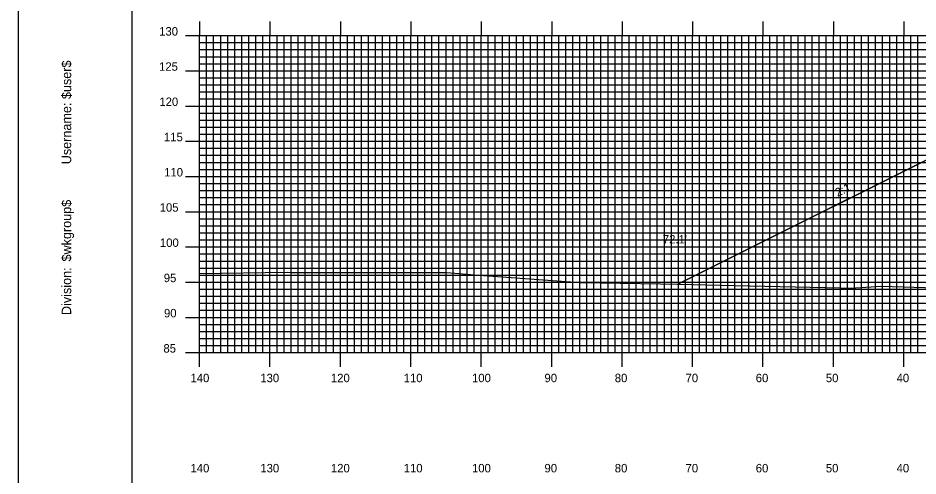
# Model space of a CAD drawing. Extents: x 1786189 to 1786532, y 442591 to 442811.
# Drawn here: x 1786188.8 to 1786316.6, y 442656.2 to 442721.2 of the extents above; entities that cross this region are included whole.
import ezdxf

# ---------------------------------------------------------------- set-up
doc = ezdxf.new("R2010")
doc.units = 0
for name, color, linetype in [('ANNOTATION', 7, 'Continuous'), ('BORDER', 7, 'Continuous'), ('D_Roadway_Centerline', 7, 'Continuous'), ('D_Roadway_SlopeLines', 7, 'Continuous'), ('D_Text_Standard', 7, 'Continuous'), ('H_V ANNOTATION', 7, 'Continuous'), ('MAJOR', 7, 'Continuous'), ('MINOR', 7, 'Continuous'), ('PLOT BOUNDARY', 7, 'Continuous'), ('S_Roadway_Centerline', 7, 'Continuous')]:
    doc.layers.add(name, color=color, linetype=linetype)

msp = doc.modelspace()

# ---------------------------------------------------------------- linework, layer by layer
at = {"layer": 'BORDER'}
msp.add_lwpolyline([(1786204.96, 442596.67), (1786524.96, 442596.67), (1786524.96, 442806.67), (1786204.96, 442806.67)], close=True, dxfattribs=at)
at = {"layer": 'D_Roadway_Centerline'}
msp.add_lwpolyline([(1786282.49, 442683.37), (1786326.75, 442705.5), (1786331.56, 442707.91), (1786334.56, 442708.03), (1786342.56, 442708.35), (1786354.56, 442708.61), (1786366.56, 442708.87), (1786374.56, 442708.55), (1786377.56, 442708.43), (1786382.31, 442706.06), (1786430.92, 442681.76)], dxfattribs=at)
at = {"layer": 'D_Roadway_SlopeLines'}
msp.add_lwpolyline([(1786331.56, 442707.91), (1786282.49, 442683.37)], dxfattribs=at)
at = {"layer": 'MAJOR'}
for p, q in [((1786214.56, 442720.67), (1786214.56, 442718.67)), ((1786224.56, 442720.67), (1786224.56, 442718.67)), ((1786234.56, 442720.67), (1786234.56, 442718.67)), ((1786244.56, 442720.67), (1786244.56, 442718.67)), ((1786254.56, 442720.67), (1786254.56, 442718.67)), ((1786264.56, 442720.67), (1786264.56, 442718.67)), ((1786274.56, 442720.67), (1786274.56, 442718.67)), ((1786284.56, 442720.67), (1786284.56, 442718.67)), ((1786294.56, 442720.67), (1786294.56, 442718.67)), ((1786304.56, 442720.67), (1786304.56, 442718.67)), ((1786314.56, 442720.67), (1786314.56, 442718.67)), ((1786212.56, 442718.67), (1786214.56, 442718.67)), ((1786214.56, 442718.67), (1786494.56, 442718.67)), ((1786214.56, 442673.67), (1786214.56, 442718.67)), ((1786214.56, 442673.67), (1786214.56, 442718.67)), ((1786214.56, 442718.67), (1786494.56, 442718.67)), ((1786224.56, 442673.67), (1786224.56, 442718.67)), ((1786234.56, 442673.67), (1786234.56, 442718.67)), ((1786244.56, 442673.67), (1786244.56, 442718.67)), ((1786254.56, 442673.67), (1786254.56, 442718.67)), ((1786264.56, 442673.67), (1786264.56, 442718.67)), ((1786274.56, 442673.67), (1786274.56, 442718.67)), ((1786284.56, 442673.67), (1786284.56, 442718.67)), ((1786294.56, 442673.67), (1786294.56, 442718.67)), ((1786304.56, 442673.67), (1786304.56, 442718.67)), ((1786314.56, 442673.67), (1786314.56, 442718.67)), ((1786212.56, 442713.67), (1786214.56, 442713.67)), ((1786214.56, 442713.67), (1786494.56, 442713.67)), ((1786212.56, 442708.67), (1786214.56, 442708.67)), ((1786214.56, 442708.67), (1786494.56, 442708.67)), ((1786212.56, 442703.67), (1786214.56, 442703.67)), ((1786214.56, 442703.67), (1786494.56, 442703.67)), ((1786212.56, 442698.67), (1786214.56, 442698.67)), ((1786214.56, 442698.67), (1786494.56, 442698.67)), ((1786212.56, 442693.67), (1786214.56, 442693.67)), ((1786214.56, 442693.67), (1786494.56, 442693.67)), ((1786212.56, 442688.67), (1786214.56, 442688.67)), ((1786214.56, 442688.67), (1786494.56, 442688.67)), ((1786212.56, 442683.67), (1786214.56, 442683.67)), ((1786214.56, 442683.67), (1786494.56, 442683.67)), ((1786212.56, 442678.67), (1786214.56, 442678.67)), ((1786214.56, 442678.67), (1786494.56, 442678.67)), ((1786212.56, 442673.67), (1786214.56, 442673.67)), ((1786214.56, 442673.67), (1786494.56, 442673.67)), ((1786214.56, 442673.67), (1786494.56, 442673.67)), ((1786214.56, 442671.66), (1786214.56, 442673.67)), ((1786224.56, 442671.66), (1786224.56, 442673.67)), ((1786234.56, 442671.66), (1786234.56, 442673.67)), ((1786244.56, 442671.66), (1786244.56, 442673.67)), ((1786254.56, 442671.66), (1786254.56, 442673.67)), ((1786264.56, 442671.66), (1786264.56, 442673.67)), ((1786274.56, 442671.66), (1786274.56, 442673.67)), ((1786284.56, 442671.66), (1786284.56, 442673.67)), ((1786294.56, 442671.66), (1786294.56, 442673.67)), ((1786304.56, 442671.66), (1786304.56, 442673.67)), ((1786314.56, 442671.66), (1786314.56, 442673.67))]:
    msp.add_line(p, q, dxfattribs=at)
at = {"layer": 'MINOR'}
for p, q in [((1786215.56, 442673.67), (1786215.56, 442718.67)), ((1786216.56, 442673.67), (1786216.56, 442718.67)), ((1786217.56, 442673.67), (1786217.56, 442718.67)), ((1786218.56, 442673.67), (1786218.56, 442718.67)), ((1786219.56, 442673.67), (1786219.56, 442718.67)), ((1786220.56, 442673.67), (1786220.56, 442718.67)), ((1786221.56, 442673.67), (1786221.56, 442718.67)), ((1786222.56, 442673.67), (1786222.56, 442718.67)), ((1786223.56, 442673.67), (1786223.56, 442718.67)), ((1786225.56, 442673.67), (1786225.56, 442718.67)), ((1786226.56, 442673.67), (1786226.56, 442718.67)), ((1786227.56, 442673.67), (1786227.56, 442718.67)), ((1786228.56, 442673.67), (1786228.56, 442718.67)), ((1786229.56, 442673.67), (1786229.56, 442718.67)), ((1786230.56, 442673.67), (1786230.56, 442718.67)), ((1786231.56, 442673.67), (1786231.56, 442718.67)), ((1786232.56, 442673.67), (1786232.56, 442718.67)), ((1786233.56, 442673.67), (1786233.56, 442718.67)), ((1786235.56, 442673.67), (1786235.56, 442718.67)), ((1786236.56, 442673.67), (1786236.56, 442718.67)), ((1786237.56, 442673.67), (1786237.56, 442718.67)), ((1786238.56, 442673.67), (1786238.56, 442718.67)), ((1786239.56, 442673.67), (1786239.56, 442718.67)), ((1786240.56, 442673.67), (1786240.56, 442718.67)), ((1786241.56, 442673.67), (1786241.56, 442718.67)), ((1786242.56, 442673.67), (1786242.56, 442718.67)), ((1786243.56, 442673.67), (1786243.56, 442718.67)), ((1786245.56, 442673.67), (1786245.56, 442718.67)), ((1786246.56, 442673.67), (1786246.56, 442718.67)), ((1786247.56, 442673.67), (1786247.56, 442718.67)), ((1786248.56, 442673.67), (1786248.56, 442718.67)), ((1786249.56, 442673.67), (1786249.56, 442718.67)), ((1786250.56, 442673.67), (1786250.56, 442718.67)), ((1786251.56, 442673.67), (1786251.56, 442718.67)), ((1786252.56, 442673.67), (1786252.56, 442718.67)), ((1786253.56, 442673.67), (1786253.56, 442718.67)), ((1786255.56, 442673.67), (1786255.56, 442718.67)), ((1786256.56, 442673.67), (1786256.56, 442718.67)), ((1786257.56, 442673.67), (1786257.56, 442718.67)), ((1786258.56, 442673.67), (1786258.56, 442718.67)), ((1786259.56, 442673.67), (1786259.56, 442718.67)), ((1786260.56, 442673.67), (1786260.56, 442718.67)), ((1786261.56, 442673.67), (1786261.56, 442718.67)), ((1786262.56, 442673.67), (1786262.56, 442718.67)), ((1786263.56, 442673.67), (1786263.56, 442718.67)), ((1786265.56, 442673.67), (1786265.56, 442718.67)), ((1786266.56, 442673.67), (1786266.56, 442718.67)), ((1786267.56, 442673.67), (1786267.56, 442718.67)), ((1786268.56, 442673.67), (1786268.56, 442718.67)), ((1786269.56, 442673.67), (1786269.56, 442718.67)), ((1786270.56, 442673.67), (1786270.56, 442718.67)), ((1786271.56, 442673.67), (1786271.56, 442718.67)), ((1786272.56, 442673.67), (1786272.56, 442718.67)), ((1786273.56, 442673.67), (1786273.56, 442718.67)), ((1786275.56, 442673.67), (1786275.56, 442718.67)), ((1786276.56, 442673.67), (1786276.56, 442718.67)), ((1786277.56, 442673.67), (1786277.56, 442718.67)), ((1786278.56, 442673.67), (1786278.56, 442718.67)), ((1786279.56, 442673.67), (1786279.56, 442718.67)), ((1786280.56, 442673.67), (1786280.56, 442718.67)), ((1786281.56, 442673.67), (1786281.56, 442718.67)), ((1786282.56, 442673.67), (1786282.56, 442718.67)), ((1786283.56, 442673.67), (1786283.56, 442718.67)), ((1786285.56, 442673.67), (1786285.56, 442718.67)), ((1786286.56, 442673.67), (1786286.56, 442718.67)), ((1786287.56, 442673.67), (1786287.56, 442718.67)), ((1786288.56, 442673.67), (1786288.56, 442718.67)), ((1786289.56, 442673.67), (1786289.56, 442718.67)), ((1786290.56, 442673.67), (1786290.56, 442718.67)), ((1786291.56, 442673.67), (1786291.56, 442718.67)), ((1786292.56, 442673.67), (1786292.56, 442718.67)), ((1786293.56, 442673.67), (1786293.56, 442718.67)), ((1786295.56, 442673.67), (1786295.56, 442718.67)), ((1786296.56, 442673.67), (1786296.56, 442718.67)), ((1786297.56, 442673.67), (1786297.56, 442718.67)), ((1786298.56, 442673.67), (1786298.56, 442718.67)), ((1786299.56, 442673.67), (1786299.56, 442718.67)), ((1786300.56, 442673.67), (1786300.56, 442718.67)), ((1786301.56, 442673.67), (1786301.56, 442718.67)), ((1786302.56, 442673.67), (1786302.56, 442718.67)), ((1786303.56, 442673.67), (1786303.56, 442718.67)), ((1786305.56, 442673.67), (1786305.56, 442718.67)), ((1786306.56, 442673.67), (1786306.56, 442718.67)), ((1786307.56, 442673.67), (1786307.56, 442718.67)), ((1786308.56, 442673.67), (1786308.56, 442718.67)), ((1786309.56, 442673.67), (1786309.56, 442718.67)), ((1786310.56, 442673.67), (1786310.56, 442718.67)), ((1786311.56, 442673.67), (1786311.56, 442718.67)), ((1786312.56, 442673.67), (1786312.56, 442718.67)), ((1786313.56, 442673.67), (1786313.56, 442718.67)), ((1786315.56, 442673.67), (1786315.56, 442718.67)), ((1786316.56, 442673.67), (1786316.56, 442718.67)), ((1786214.56, 442717.67), (1786494.56, 442717.67)), ((1786214.56, 442717.67), (1786216.57, 442717.67)), ((1786214.56, 442716.67), (1786494.56, 442716.67)), ((1786214.56, 442716.67), (1786216.57, 442716.67)), ((1786214.56, 442715.67), (1786494.56, 442715.67)), ((1786214.56, 442715.67), (1786216.57, 442715.67)), ((1786214.56, 442714.67), (1786494.56, 442714.67)), ((1786214.56, 442714.67), (1786216.57, 442714.67)), ((1786214.56, 442712.67), (1786494.56, 442712.67)), ((1786214.56, 442712.67), (1786216.57, 442712.67)), ((1786214.56, 442711.67), (1786494.56, 442711.67)), ((1786214.56, 442711.67), (1786216.57, 442711.67)), ((1786214.56, 442710.67), (1786494.56, 442710.67)), ((1786214.56, 442710.67), (1786216.57, 442710.67)), ((1786214.56, 442709.67), (1786494.56, 442709.67)), ((1786214.56, 442709.67), (1786216.57, 442709.67)), ((1786214.56, 442707.67), (1786494.56, 442707.67)), ((1786214.56, 442707.67), (1786216.57, 442707.67)), ((1786214.56, 442706.67), (1786494.56, 442706.67)), ((1786214.56, 442706.67), (1786216.57, 442706.67)), ((1786214.56, 442705.67), (1786494.56, 442705.67)), ((1786214.56, 442705.67), (1786216.57, 442705.67)), ((1786214.56, 442704.67), (1786494.56, 442704.67)), ((1786214.56, 442704.67), (1786216.57, 442704.67)), ((1786214.56, 442702.67), (1786494.56, 442702.67)), ((1786214.56, 442702.67), (1786216.57, 442702.67)), ((1786214.56, 442701.67), (1786494.56, 442701.67)), ((1786214.56, 442701.67), (1786216.57, 442701.67)), ((1786214.56, 442700.67), (1786494.56, 442700.67)), ((1786214.56, 442700.67), (1786216.57, 442700.67)), ((1786214.56, 442699.67), (1786494.56, 442699.67)), ((1786214.56, 442699.67), (1786216.57, 442699.67)), ((1786214.56, 442697.67), (1786494.56, 442697.67)), ((1786214.56, 442697.67), (1786216.57, 442697.67)), ((1786214.56, 442696.67), (1786494.56, 442696.67)), ((1786214.56, 442696.67), (1786216.57, 442696.67)), ((1786214.56, 442695.67), (1786494.56, 442695.67)), ((1786214.56, 442695.67), (1786216.57, 442695.67)), ((1786214.56, 442694.67), (1786494.56, 442694.67)), ((1786214.56, 442694.67), (1786216.57, 442694.67)), ((1786214.56, 442692.67), (1786494.56, 442692.67)), ((1786214.56, 442692.67), (1786216.57, 442692.67)), ((1786214.56, 442691.67), (1786494.56, 442691.67)), ((1786214.56, 442691.67), (1786216.57, 442691.67)), ((1786214.56, 442690.67), (1786494.56, 442690.67)), ((1786214.56, 442690.67), (1786216.57, 442690.67)), ((1786214.56, 442689.67), (1786494.56, 442689.67)), ((1786214.56, 442689.67), (1786216.57, 442689.67)), ((1786214.56, 442687.67), (1786494.56, 442687.67)), ((1786214.56, 442687.67), (1786216.57, 442687.67)), ((1786214.56, 442686.67), (1786494.56, 442686.67)), ((1786214.56, 442686.67), (1786216.57, 442686.67)), ((1786214.56, 442685.67), (1786494.56, 442685.67)), ((1786214.56, 442685.67), (1786216.57, 442685.67)), ((1786214.56, 442684.67), (1786494.56, 442684.67)), ((1786214.56, 442684.67), (1786216.57, 442684.67)), ((1786214.56, 442682.67), (1786494.56, 442682.67)), ((1786214.56, 442682.67), (1786216.57, 442682.67)), ((1786214.56, 442681.67), (1786494.56, 442681.67)), ((1786214.56, 442681.67), (1786216.57, 442681.67)), ((1786214.56, 442680.67), (1786494.56, 442680.67)), ((1786214.56, 442680.67), (1786216.57, 442680.67)), ((1786214.56, 442679.67), (1786494.56, 442679.67)), ((1786214.56, 442679.67), (1786216.57, 442679.67)), ((1786214.56, 442677.67), (1786494.56, 442677.67)), ((1786214.56, 442677.67), (1786216.57, 442677.67)), ((1786214.56, 442676.67), (1786494.56, 442676.67)), ((1786214.56, 442676.67), (1786216.57, 442676.67)), ((1786214.56, 442675.67), (1786494.56, 442675.67)), ((1786214.56, 442675.67), (1786216.57, 442675.67)), ((1786214.56, 442674.67), (1786494.56, 442674.67)), ((1786214.56, 442674.67), (1786216.57, 442674.67))]:
    msp.add_line(p, q, dxfattribs=at)
at = {"layer": 'PLOT BOUNDARY'}
msp.add_lwpolyline([(1786188.78, 442590.55), (1786528.78, 442590.55), (1786528.78, 442810.55), (1786188.78, 442810.55)], close=True, dxfattribs=at)
at = {"layer": 'S_Roadway_Centerline'}
msp.add_lwpolyline([(1786214.56, 442684.9), (1786226.99, 442685.07), (1786227.56, 442685.06), (1786227.94, 442685.05), (1786246.77, 442685.03), (1786249.69, 442685.03), (1786253.62, 442684.7), (1786268.56, 442683.62), (1786280.01, 442683.43), (1786284.68, 442683.32), (1786288.43, 442683.26), (1786307.65, 442682.83), (1786307.73, 442682.84), (1786311.37, 442683.11), (1786329.96, 442682.55)], dxfattribs=at)

# ---------------------------------------------------------------- texts
at = {"layer": 'ANNOTATION'}
msp.add_text('2:1', height=1.2, rotation=26.5651, dxfattribs=at).set_placement((1786305.17, 442695.75))
at = {"layer": 'BORDER'}
for s, p in [('$user$', (1786196.33, 442709.65)), ('Username:', (1786196.33, 442700.4)), ('$wkgroup$', (1786196.33, 442686.6)), ('Division:', (1786196.33, 442679))]:
    msp.add_text(s, height=1.339, rotation=90, dxfattribs=at).set_placement(p)
at = {"layer": 'D_Text_Standard'}
msp.add_text("72.1'", height=1.2, dxfattribs=at).set_placement((1786280.35, 442689.16))
at = {"layer": 'H_V ANNOTATION'}
for s, p in [('130', (1786208.82, 442718.67)), ('125', (1786208.81, 442713.67)), ('120', (1786208.85, 442708.67)), ('115', (1786209.5, 442703.67)), ('110', (1786209.53, 442698.67)), ('105', (1786208.9, 442693.67)), ('100', (1786208.93, 442688.67)), ('95', (1786209.48, 442683.67)), ('90', (1786209.51, 442678.67)), ('85', (1786209.43, 442673.67)), ('140', (1786213.27, 442669.47)), ('130', (1786223.19, 442669.47)), ('120', (1786233.21, 442669.47)), ('110', (1786243.55, 442669.47)), ('100', (1786253.25, 442669.47)), ('90', (1786263.54, 442669.47)), ('80', (1786273.52, 442669.47)), ('70', (1786283.57, 442669.47)), ('60', (1786293.54, 442669.47)), ('50', (1786303.49, 442669.47)), ('40', (1786313.54, 442669.47)), ('140', (1786213.27, 442656.67)), ('130', (1786223.19, 442656.67)), ('120', (1786233.21, 442656.67)), ('110', (1786243.55, 442656.67)), ('100', (1786253.25, 442656.67)), ('90', (1786263.54, 442656.67)), ('80', (1786273.52, 442656.67)), ('70', (1786283.57, 442656.67)), ('60', (1786293.54, 442656.67)), ('50', (1786303.49, 442656.67)), ('40', (1786313.54, 442656.67))]:
    msp.add_text(s, height=1.2, dxfattribs=at).set_placement(p)
at = {"layer": 'MAJOR'}
msp.add_text('-', height=0.012, dxfattribs=at).set_placement((1786214.56, 442673.67))

doc.saveas('drawing.dxf')
